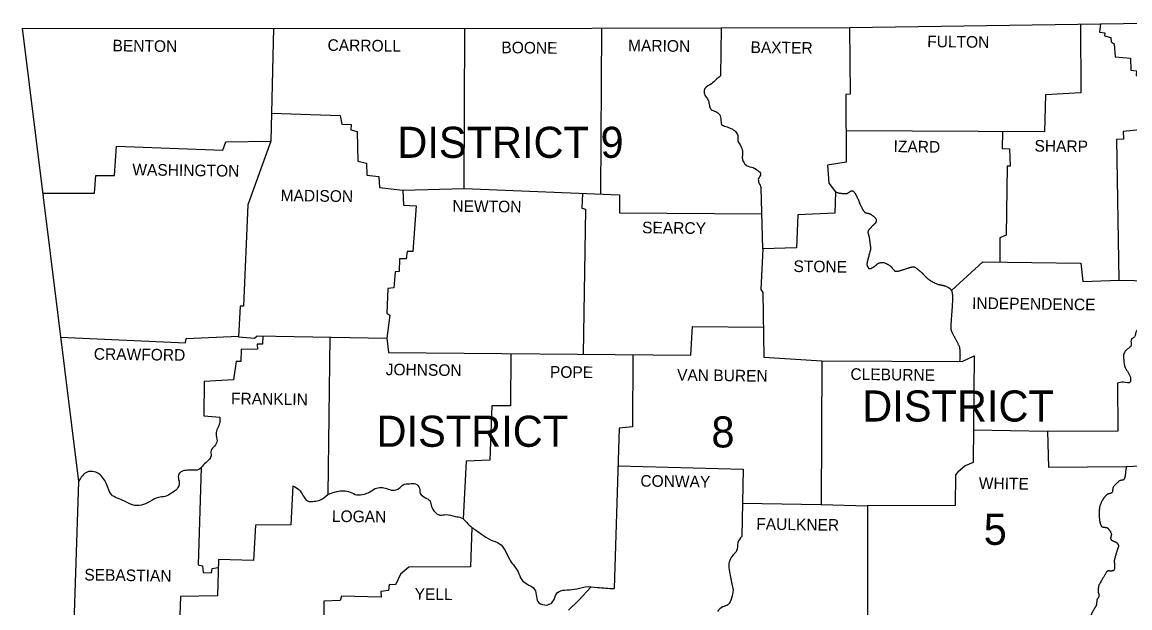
# Model space of a CAD drawing. Extents: x -0.96 to 2.36, y -0.12 to 0.92.
# Drawn here: x 1.0951 to 1.2805, y 0.7208 to 0.8188 of the extents above; entities that cross this region are included whole.
import ezdxf

# ---------------------------------------------------------------- set-up
doc = ezdxf.new("R2010")
doc.units = 0
doc.layers.add('SHET_Annotations', color=7, linetype='Continuous')

msp = doc.modelspace()

# ---------------------------------------------------------------- linework, layer by layer
at = {"layer": 'SHET_Annotations'}
msp.add_line((1.27998, 0.74445), (1.28519, 0.74474), dxfattribs=at)
for points in [[(1.0951, 0.81784), (1.16886, 0.81779), (1.23364, 0.81792), (1.31002, 0.81908), (1.34545, 0.81991)], [(1.0951, 0.81784), (1.10454, 0.74198), (1.10045, 0.61817)], [(1.1372, 0.81781), (1.13672, 0.79894)], [(1.19207, 0.81783), (1.19191, 0.79004)], [(1.21215, 0.81787), (1.21204, 0.80983)], [(1.23361, 0.81792), (1.23372, 0.80679), (1.23297, 0.80674), (1.23307, 0.79538), (1.22991, 0.79491), (1.23017, 0.79188), (1.23126, 0.79045), (1.23118, 0.78685), (1.22498, 0.78661), (1.22475, 0.78106), (1.21909, 0.78088), (1.21878, 0.77409), (1.21912, 0.77357), (1.21928, 0.76278), (1.229, 0.76213), (1.22887, 0.73809), (1.23665, 0.73788), (1.23665, 0.7134), (1.23053, 0.71293), (1.23009, 0.70759), (1.21979, 0.70751)], [(1.27228, 0.81851), (1.27236, 0.80702), (1.26642, 0.80669), (1.26627, 0.80049), (1.23302, 0.80065)], [(1.27561, 0.81856), (1.27545, 0.81716), (1.27636, 0.81703), (1.27628, 0.81652), (1.27734, 0.81628), (1.27742, 0.81553), (1.27794, 0.81522), (1.27807, 0.81304), (1.28066, 0.81278), (1.28069, 0.81078), (1.28165, 0.81068), (1.28162, 0.8099), (1.28245, 0.80964), (1.28243, 0.807), (1.28313, 0.80687), (1.28331, 0.8009), (1.27944, 0.80054), (1.2795, 0.79927), (1.27833, 0.79919), (1.27872, 0.77567), (1.2971, 0.77525), (1.29742, 0.73864), (1.28541, 0.73832), (1.28519, 0.74474)], [(1.13684, 0.80358), (1.14835, 0.80321), (1.14861, 0.80176), (1.15019, 0.80171), (1.15014, 0.80083), (1.1512, 0.80054), (1.1513, 0.79554), (1.15273, 0.79522), (1.15283, 0.79325), (1.1548, 0.79299), (1.15491, 0.79115), (1.15885, 0.79073), (1.16912, 0.791), (1.1692, 0.81779)], [(1.25922, 0.80052), (1.25916, 0.79769), (1.26041, 0.79761), (1.26049, 0.79471), (1.25999, 0.79471), (1.25984, 0.78319), (1.25877, 0.78272), (1.25877, 0.77869)], [(1.09854, 0.79022), (1.10724, 0.79019), (1.10745, 0.79318), (1.11059, 0.79318), (1.11087, 0.79805), (1.12869, 0.79743), (1.12921, 0.79878), (1.13672, 0.79894), (1.13289, 0.78825), (1.13214, 0.77131), (1.13159, 0.77129), (1.13133, 0.76618), (1.134, 0.76594), (1.13442, 0.76636), (1.15618, 0.76594), (1.15641, 0.76353)], [(1.15885, 0.79073), (1.15895, 0.7882), (1.16105, 0.78809), (1.16051, 0.78042), (1.15955, 0.78044), (1.15937, 0.77922), (1.15828, 0.7792), (1.15823, 0.77712), (1.15755, 0.77707), (1.15732, 0.77437), (1.15631, 0.77424), (1.15618, 0.77015), (1.15664, 0.76981), (1.15618, 0.76594)], [(1.16912, 0.791), (1.19511, 0.78991), (1.19508, 0.78693), (1.21895, 0.78677)], [(1.18889, 0.79017), (1.1888, 0.78768), (1.18943, 0.78752), (1.18903, 0.76325)], [(1.21909, 0.78088), (1.21883, 0.79113)], [(1.25066, 0.77392), (1.25595, 0.77873), (1.27236, 0.77847), (1.27267, 0.77544), (1.27872, 0.77567)], [(1.15641, 0.76353), (1.20706, 0.76309), (1.20732, 0.76792), (1.2192, 0.76776)], [(1.10154, 0.76613), (1.12246, 0.76514), (1.12257, 0.76589), (1.13134, 0.76629)], [(1.13537, 0.76634), (1.13533, 0.76493), (1.13447, 0.76493), (1.1345, 0.7641), (1.13175, 0.76405), (1.1317, 0.76203), (1.13092, 0.76203), (1.13048, 0.75897), (1.12555, 0.75871), (1.12552, 0.75295), (1.12817, 0.75274)], [(1.14661, 0.76613), (1.14627, 0.73978)], [(1.1769, 0.76335), (1.17685, 0.75464), (1.17371, 0.75459), (1.17342, 0.74551), (1.16943, 0.74535), (1.16895, 0.73569)], [(1.19736, 0.76318), (1.19728, 0.75108), (1.19505, 0.75088), (1.19422, 0.72403)], [(1.229, 0.76213), (1.25247, 0.76203), (1.25447, 0.76296), (1.25434, 0.74515), (1.25299, 0.74455), (1.25175, 0.74349), (1.25136, 0.74307), (1.25128, 0.73796), (1.23665, 0.73788)], [(1.27848, 0.75842), (1.27856, 0.75038), (1.26674, 0.75033), (1.25438, 0.75057)], [(1.26674, 0.75033), (1.26692, 0.74434), (1.27998, 0.74445)], [(1.12507, 0.74427), (1.12459, 0.728), (1.12532, 0.72782), (1.12542, 0.72673), (1.12682, 0.72665), (1.12692, 0.72741), (1.12792, 0.72757)], [(1.19486, 0.74455), (1.21583, 0.74403), (1.21557, 0.73277)], [(1.27998, 0.74445), (1.27986, 0.74395)], [(1.14041, 0.74123), (1.1401, 0.73472), (1.13416, 0.73467), (1.13382, 0.72873), (1.12796, 0.72888), (1.12778, 0.72279), (1.12161, 0.72271), (1.1214, 0.71659), (1.12532, 0.71638), (1.12516, 0.71449), (1.14557, 0.71393)], [(1.21569, 0.7383), (1.22887, 0.73809)], [(1.17039, 0.73425), (1.17018, 0.72769), (1.15981, 0.72764), (1.15843, 0.72647), (1.15763, 0.72466), (1.15652, 0.72471), (1.15646, 0.7237), (1.15514, 0.72354), (1.15519, 0.72261), (1.14858, 0.72276), (1.14832, 0.72204), (1.1456, 0.72193), (1.14557, 0.71393)], [(1.19036, 0.7243), (1.18831, 0.72209), (1.18655, 0.7204)]]:
    msp.add_lwpolyline(points, dxfattribs=at)
for points in [[(1.21204, 0.80983), (1.21121, 0.80918), (1.21051, 0.80853), (1.20939, 0.80772), (1.20927, 0.807), (1.20963, 0.8063), (1.20999, 0.8057), (1.21015, 0.80487), (1.21046, 0.8042), (1.21121, 0.80389), (1.21188, 0.80332), (1.21209, 0.80251), (1.2122, 0.80173), (1.2129, 0.80137), (1.21373, 0.80106), (1.21453, 0.80051), (1.21489, 0.79987), (1.21494, 0.79896), (1.21528, 0.79831), (1.21565, 0.79745), (1.21572, 0.79678), (1.21565, 0.79611), (1.21585, 0.79546), (1.21642, 0.79481), (1.21746, 0.7945), (1.21821, 0.79406), (1.21873, 0.79341), (1.21837, 0.79266), (1.21845, 0.79196), (1.21883, 0.79113)], [(1.28698, 0.77548), (1.28613, 0.77341), (1.28546, 0.77204), (1.28507, 0.77085), (1.28419, 0.77017), (1.2839, 0.76952), (1.28315, 0.76926), (1.28256, 0.76836), (1.2823, 0.76755), (1.28165, 0.76719), (1.28131, 0.76615), (1.28074, 0.76561), (1.28077, 0.7647), (1.28009, 0.76408), (1.27955, 0.76335), (1.27952, 0.76231), (1.27978, 0.76102), (1.28025, 0.76021), (1.28064, 0.75923), (1.28061, 0.75858), (1.27947, 0.75858), (1.27848, 0.75842)], [(1.12817, 0.75274), (1.12817, 0.75178), (1.12781, 0.7508), (1.12757, 0.74992), (1.12773, 0.74878), (1.12731, 0.74787), (1.12672, 0.74712), (1.12672, 0.74623), (1.12604, 0.74527), (1.12529, 0.74452), (1.12467, 0.74395), (1.1235, 0.74387), (1.12254, 0.74382), (1.12161, 0.74349), (1.12124, 0.74279), (1.1214, 0.74175), (1.12104, 0.74074), (1.1201, 0.73998), (1.11904, 0.73947), (1.11795, 0.73928), (1.11642, 0.73856), (1.11507, 0.73799), (1.11359, 0.73804), (1.11225, 0.73864), (1.111, 0.73918), (1.11004, 0.73975), (1.10929, 0.74141), (1.10877, 0.74234), (1.10789, 0.74328), (1.10688, 0.74364), (1.106, 0.74354), (1.10454, 0.74198)], [(1.14041, 0.74123), (1.1414, 0.74061), (1.14217, 0.73957), (1.14285, 0.73869), (1.14401, 0.73864), (1.14492, 0.73882), (1.14627, 0.73978)], [(1.14627, 0.73978), (1.1478, 0.74027), (1.14889, 0.7404), (1.15001, 0.74019), (1.15115, 0.73972), (1.15234, 0.73985), (1.15325, 0.74017), (1.15418, 0.74076), (1.15517, 0.74094), (1.15615, 0.74076), (1.15716, 0.74048), (1.15823, 0.74081), (1.15888, 0.74138), (1.15996, 0.74159), (1.16095, 0.74159), (1.16162, 0.74081), (1.16175, 0.73996), (1.16264, 0.73921), (1.16339, 0.73869), (1.16365, 0.73775), (1.16404, 0.73705), (1.16445, 0.73659), (1.16505, 0.73633), (1.16606, 0.73641), (1.16761, 0.73609), (1.1686, 0.73589), (1.16953, 0.73508), (1.17039, 0.73425)], [(1.17039, 0.73425), (1.172, 0.73316), (1.1735, 0.7322), (1.17503, 0.73153), (1.17589, 0.73054), (1.17667, 0.72896), (1.17734, 0.728), (1.17812, 0.72681), (1.17874, 0.72551), (1.17967, 0.72476), (1.18069, 0.72414), (1.18118, 0.723), (1.18141, 0.72186), (1.18253, 0.72129), (1.18359, 0.72152), (1.18416, 0.72222), (1.18473, 0.72339), (1.18595, 0.72378), (1.18753, 0.72391), (1.18935, 0.72432), (1.1914, 0.72424), (1.19422, 0.72403)], [(1.21557, 0.73277), (1.21494, 0.73171), (1.21471, 0.73034), (1.21396, 0.72946), (1.21349, 0.7285), (1.21347, 0.72715), (1.21367, 0.72595), (1.21391, 0.72484), (1.21411, 0.72378), (1.21386, 0.72245), (1.21326, 0.72131), (1.21238, 0.72097), (1.2115, 0.7202)]]:
    msp.add_spline(points, degree=3, dxfattribs=at)
for points in [[(1.23126, 0.79045), (1.2314, 0.79038), (1.23155, 0.79032), (1.2317, 0.79029), (1.23185, 0.79025), (1.23201, 0.79021), (1.23216, 0.7902), (1.23231, 0.79018), (1.23247, 0.79017), (1.23262, 0.79016), (1.23277, 0.79015), (1.23292, 0.79014), (1.23307, 0.79014), (1.23317, 0.79014), (1.23327, 0.79018), (1.23336, 0.79024), (1.23347, 0.7903), (1.23355, 0.79038), (1.23365, 0.79045), (1.23374, 0.7905), (1.23383, 0.79056), (1.23393, 0.7906), (1.23397, 0.79062), (1.23402, 0.79062), (1.23406, 0.79062), (1.23411, 0.79061), (1.23415, 0.79059), (1.23419, 0.79056), (1.23439, 0.79038), (1.23454, 0.7902), (1.23465, 0.78999), (1.23471, 0.78988), (1.23477, 0.78978), (1.23482, 0.78967), (1.23487, 0.78956), (1.23492, 0.78945), (1.23497, 0.78934), (1.2351, 0.78904), (1.23522, 0.78873), (1.23536, 0.78843), (1.23545, 0.7882), (1.23556, 0.78798), (1.23567, 0.78776), (1.23572, 0.78765), (1.23578, 0.78755), (1.23584, 0.78744), (1.23588, 0.78739), (1.23591, 0.78734), (1.23595, 0.78729), (1.23598, 0.78723), (1.23602, 0.78718), (1.23606, 0.78713), (1.23612, 0.78706), (1.23619, 0.78699), (1.23628, 0.78696), (1.23637, 0.78692), (1.23647, 0.78689), (1.23656, 0.78687), (1.23666, 0.78685), (1.23677, 0.78683), (1.23687, 0.7868), (1.23691, 0.78679), (1.23696, 0.78678), (1.23701, 0.78676), (1.23706, 0.78674), (1.2371, 0.78672), (1.23714, 0.78669), (1.2373, 0.7866), (1.23745, 0.78649), (1.23759, 0.78638), (1.23767, 0.78632), (1.23773, 0.78626), (1.2378, 0.7862), (1.23786, 0.78613), (1.23792, 0.78607), (1.23797, 0.78599), (1.23801, 0.78594), (1.23804, 0.78588), (1.23806, 0.78581), (1.23808, 0.78574), (1.23809, 0.78567), (1.23808, 0.7856), (1.23807, 0.7855), (1.23805, 0.78539), (1.238, 0.7853), (1.23799, 0.78527), (1.23797, 0.78524), (1.23795, 0.78521), (1.23789, 0.78515), (1.23784, 0.78508), (1.23778, 0.78503), (1.23772, 0.78497), (1.23765, 0.78491), (1.23759, 0.78485), (1.23753, 0.78479), (1.23746, 0.78474), (1.2374, 0.78468), (1.23734, 0.78462), (1.23728, 0.78455), (1.23722, 0.78449), (1.2372, 0.78446), (1.23717, 0.78443), (1.23714, 0.7844), (1.23706, 0.78431), (1.23697, 0.78422), (1.23689, 0.78413), (1.23684, 0.78408), (1.2368, 0.78401), (1.23676, 0.78394), (1.23674, 0.78391), (1.23673, 0.78388), (1.23672, 0.78384), (1.23671, 0.78381), (1.2367, 0.78377), (1.2367, 0.78374), (1.2367, 0.78366), (1.23671, 0.78359), (1.23672, 0.78352), (1.23674, 0.78344), (1.23676, 0.78337), (1.23678, 0.7833), (1.2368, 0.78322), (1.23682, 0.78315), (1.23684, 0.78308), (1.23685, 0.783), (1.23687, 0.78293), (1.23689, 0.78285), (1.23692, 0.78266), (1.23695, 0.78246), (1.23698, 0.78226), (1.23701, 0.78206), (1.23704, 0.78186), (1.23707, 0.78166), (1.23712, 0.78129), (1.23715, 0.78091), (1.23707, 0.78055), (1.23698, 0.78019), (1.23687, 0.77984), (1.23678, 0.77948), (1.2367, 0.77917), (1.23662, 0.77887), (1.23655, 0.77855), (1.23653, 0.77848), (1.23652, 0.7784), (1.23652, 0.77833), (1.23652, 0.77826), (1.23653, 0.77819), (1.23655, 0.77812), (1.23657, 0.77804), (1.2366, 0.77797), (1.23664, 0.7779), (1.23666, 0.77787), (1.23668, 0.77783), (1.2367, 0.7778), (1.23673, 0.77776), (1.23675, 0.77773), (1.23678, 0.77769), (1.23681, 0.77766), (1.23684, 0.77764), (1.23687, 0.77761), (1.23691, 0.77759), (1.23694, 0.77758), (1.23698, 0.77758), (1.23705, 0.77758), (1.23713, 0.77759), (1.2372, 0.77762), (1.23736, 0.77769), (1.2375, 0.77776), (1.23764, 0.77785), (1.23768, 0.77787), (1.23772, 0.7779), (1.23776, 0.77792), (1.2378, 0.77795), (1.23783, 0.77798), (1.23787, 0.77801), (1.23795, 0.77807), (1.23802, 0.77814), (1.23809, 0.7782), (1.23817, 0.77827), (1.23824, 0.77833), (1.23832, 0.77839), (1.2384, 0.77845), (1.23848, 0.77849), (1.23857, 0.77852), (1.23887, 0.77863), (1.23923, 0.77864), (1.23953, 0.77852), (1.23969, 0.77846), (1.23985, 0.77839), (1.24, 0.7783), (1.24015, 0.77822), (1.2403, 0.77813), (1.24044, 0.77803), (1.24053, 0.77796), (1.24061, 0.77789), (1.24068, 0.7778), (1.24075, 0.77771), (1.24081, 0.77761), (1.24089, 0.77752), (1.24096, 0.77744), (1.24103, 0.77735), (1.24111, 0.77728), (1.24114, 0.77724), (1.24119, 0.77722), (1.24123, 0.77719), (1.24125, 0.77718), (1.24128, 0.77717), (1.2413, 0.77716), (1.24132, 0.77716), (1.24135, 0.77715), (1.24137, 0.77715), (1.24153, 0.77713), (1.2417, 0.77714), (1.24185, 0.77719), (1.24201, 0.77723), (1.24217, 0.77728), (1.24233, 0.77733), (1.2426, 0.77742), (1.24287, 0.7775), (1.24314, 0.77759), (1.24332, 0.77765), (1.2435, 0.7777), (1.24368, 0.77776), (1.24377, 0.77779), (1.24386, 0.77781), (1.24395, 0.77783), (1.244, 0.77784), (1.24404, 0.77785), (1.24409, 0.77786), (1.24413, 0.77786), (1.24418, 0.77787), (1.24422, 0.77787), (1.24436, 0.77788), (1.24451, 0.77784), (1.24463, 0.77776), (1.24476, 0.77767), (1.24488, 0.77758), (1.245, 0.77749), (1.24512, 0.7774), (1.24524, 0.77731), (1.24535, 0.77722), (1.24546, 0.77713), (1.24557, 0.77704), (1.24568, 0.77694), (1.24575, 0.77687), (1.24582, 0.7768), (1.24589, 0.77673), (1.24596, 0.77666), (1.24602, 0.77658), (1.24609, 0.77651), (1.24616, 0.77644), (1.24622, 0.77637), (1.24629, 0.77629), (1.24636, 0.77622), (1.24643, 0.77615), (1.24651, 0.77608), (1.24675, 0.77587), (1.24701, 0.77568), (1.24728, 0.77551), (1.2476, 0.77532), (1.24793, 0.77516), (1.24827, 0.77502), (1.24837, 0.77498), (1.24847, 0.77495), (1.24857, 0.77492), (1.24868, 0.7749), (1.24878, 0.77488), (1.24889, 0.77486), (1.24899, 0.77484), (1.2491, 0.77482), (1.2492, 0.7748), (1.24931, 0.77478), (1.24941, 0.77474), (1.24952, 0.77471), (1.24974, 0.77464), (1.24995, 0.77455), (1.25016, 0.77443), (1.25027, 0.77437), (1.25036, 0.7743), (1.25044, 0.77422), (1.25049, 0.77418), (1.25052, 0.77414), (1.25056, 0.77409), (1.25058, 0.77406), (1.25059, 0.77404), (1.25061, 0.77401), (1.25063, 0.77399), (1.25064, 0.77396), (1.25066, 0.77393), (1.25068, 0.77388), (1.25071, 0.77383), (1.25073, 0.77377), (1.25078, 0.77361), (1.25082, 0.77344), (1.25083, 0.77327), (1.25084, 0.77316), (1.25084, 0.77305), (1.25084, 0.77294), (1.25084, 0.77283), (1.25084, 0.77272), (1.25084, 0.77261), (1.25084, 0.77242), (1.25084, 0.77223), (1.25083, 0.77204), (1.25083, 0.77185), (1.25082, 0.77166), (1.25081, 0.77147), (1.25078, 0.77099), (1.25074, 0.77052), (1.25071, 0.77004), (1.25067, 0.76953), (1.25064, 0.76902), (1.2506, 0.76851), (1.2506, 0.76838), (1.25059, 0.76825), (1.25058, 0.76813), (1.25057, 0.768), (1.25057, 0.76787), (1.25057, 0.76774), (1.25057, 0.76761), (1.25058, 0.76748), (1.25061, 0.76735), (1.25064, 0.76722), (1.25068, 0.7671), (1.25073, 0.76698), (1.25082, 0.76681), (1.2509, 0.76665), (1.25099, 0.76648), (1.25108, 0.76632), (1.25117, 0.76616), (1.25125, 0.766), (1.25136, 0.7658), (1.25146, 0.7656), (1.25156, 0.7654), (1.25167, 0.7652), (1.25177, 0.765), (1.25188, 0.7648), (1.25196, 0.76463), (1.25201, 0.76445), (1.25203, 0.76426), (1.25205, 0.76416), (1.25206, 0.76407), (1.25206, 0.76397), (1.25207, 0.76388), (1.25208, 0.76378), (1.25208, 0.76369), (1.2521, 0.76341), (1.25211, 0.76314), (1.25211, 0.76286), (1.2521, 0.76258), (1.25208, 0.7623), (1.25204, 0.76203)], [(1.27986, 0.74395), (1.27985, 0.74382), (1.27984, 0.7437), (1.27983, 0.74357), (1.27982, 0.74344), (1.27981, 0.74331), (1.27979, 0.74318), (1.27978, 0.74305), (1.27976, 0.74293), (1.27973, 0.7428), (1.27972, 0.74274), (1.2797, 0.74267), (1.27968, 0.74261), (1.27968, 0.74258), (1.27967, 0.74255), (1.27966, 0.74252), (1.27965, 0.74248), (1.27964, 0.74245), (1.27962, 0.74242), (1.2796, 0.74235), (1.27954, 0.74229), (1.27948, 0.74225), (1.2794, 0.74221), (1.27932, 0.74219), (1.27924, 0.74217), (1.27915, 0.74215), (1.27906, 0.74214), (1.27897, 0.74211), (1.27893, 0.7421), (1.27889, 0.74209), (1.27885, 0.74207), (1.27881, 0.74205), (1.27878, 0.74203), (1.27874, 0.74201), (1.27856, 0.74186), (1.2784, 0.74171), (1.27823, 0.74154), (1.27807, 0.74138), (1.27792, 0.74122), (1.27778, 0.74102), (1.27774, 0.74095), (1.2777, 0.74088), (1.27769, 0.7408), (1.27768, 0.74072), (1.27767, 0.74063), (1.27766, 0.74055), (1.27765, 0.74046), (1.27764, 0.74038), (1.27763, 0.7403), (1.27762, 0.74022), (1.27758, 0.74015), (1.27752, 0.74009), (1.27747, 0.74003), (1.27742, 0.73999), (1.27735, 0.73997), (1.27727, 0.73995), (1.2772, 0.73993), (1.27713, 0.73991), (1.27706, 0.73989), (1.27698, 0.73988), (1.27691, 0.73986), (1.27684, 0.73984), (1.27677, 0.7398), (1.27672, 0.73975), (1.27664, 0.73968), (1.27657, 0.73961), (1.27649, 0.73953), (1.27642, 0.73945), (1.27635, 0.73938), (1.27628, 0.7393), (1.27621, 0.73921), (1.27615, 0.73913), (1.27609, 0.73904), (1.27602, 0.73895), (1.27597, 0.73886), (1.27592, 0.73877), (1.2758, 0.73856), (1.27571, 0.73834), (1.27562, 0.73812), (1.27554, 0.7379), (1.27547, 0.73767), (1.27545, 0.73744), (1.27541, 0.73699), (1.2754, 0.73654), (1.27542, 0.73609), (1.27543, 0.73596), (1.27544, 0.73583), (1.27545, 0.7357), (1.27546, 0.73557), (1.27548, 0.73544), (1.2755, 0.73531), (1.27552, 0.73518), (1.27555, 0.73505), (1.27559, 0.73492), (1.27561, 0.73486), (1.27563, 0.73479), (1.27565, 0.73473), (1.27568, 0.73466), (1.2757, 0.7346), (1.27573, 0.73454), (1.27578, 0.73445), (1.27586, 0.73438), (1.27595, 0.73435), (1.27605, 0.73433), (1.27616, 0.73431), (1.27627, 0.7343), (1.27638, 0.73428), (1.27649, 0.73428), (1.2766, 0.73426), (1.2767, 0.73425), (1.2768, 0.7342), (1.27688, 0.73412), (1.27691, 0.73409), (1.27694, 0.73406), (1.27696, 0.73402), (1.27699, 0.73399), (1.27702, 0.73396), (1.27705, 0.73392), (1.2771, 0.73385), (1.27715, 0.73378), (1.2772, 0.7337), (1.27729, 0.73356), (1.27736, 0.73341), (1.27742, 0.73324), (1.27745, 0.73316), (1.27745, 0.73308), (1.27744, 0.73301), (1.27742, 0.73292), (1.2774, 0.73284), (1.27738, 0.73275), (1.27736, 0.73267), (1.27735, 0.73259), (1.27733, 0.73251), (1.27732, 0.73243), (1.27734, 0.73236), (1.27737, 0.73228), (1.27739, 0.73223), (1.27742, 0.7322), (1.27746, 0.73216), (1.2775, 0.73213), (1.27753, 0.7321), (1.27758, 0.73208), (1.27768, 0.73203), (1.27778, 0.73199), (1.27788, 0.73195), (1.27798, 0.73191), (1.27809, 0.73187), (1.27819, 0.73182), (1.27829, 0.73178), (1.27837, 0.7317), (1.27843, 0.73161), (1.27846, 0.73157), (1.27849, 0.73152), (1.27852, 0.73148), (1.27854, 0.73144), (1.27857, 0.73139), (1.27859, 0.73135), (1.27862, 0.73131), (1.27863, 0.73127), (1.27864, 0.73122), (1.27865, 0.73118), (1.27865, 0.73113), (1.27864, 0.73109), (1.27863, 0.73104), (1.27861, 0.73099), (1.27859, 0.73094), (1.27858, 0.73089), (1.27856, 0.73084), (1.27854, 0.73079), (1.27852, 0.73074), (1.2785, 0.73069), (1.27848, 0.73064), (1.27846, 0.73059), (1.27845, 0.73054), (1.27843, 0.73049), (1.27834, 0.73022), (1.27826, 0.72994), (1.27818, 0.72966), (1.2781, 0.72938), (1.27803, 0.7291), (1.27796, 0.72881), (1.27794, 0.72871), (1.27794, 0.72862), (1.27794, 0.72852), (1.27794, 0.72843), (1.27795, 0.72833), (1.27795, 0.72824), (1.27796, 0.72814), (1.27797, 0.72805), (1.27798, 0.72795), (1.27799, 0.72786), (1.27799, 0.72776), (1.27799, 0.72767), (1.27799, 0.72758), (1.27798, 0.72749), (1.27797, 0.7274), (1.27796, 0.72736), (1.27795, 0.72732), (1.27794, 0.72727), (1.27792, 0.72723), (1.27791, 0.72719), (1.27789, 0.72715), (1.27783, 0.72706), (1.27775, 0.72698), (1.27765, 0.72698), (1.27753, 0.72697), (1.27741, 0.72697), (1.27729, 0.72697), (1.27717, 0.72697), (1.27705, 0.72698), (1.27693, 0.72698), (1.27683, 0.72698), (1.27672, 0.72692), (1.27667, 0.72684), (1.27653, 0.72663), (1.27641, 0.72642), (1.27629, 0.72622), (1.27616, 0.72601), (1.27604, 0.7258), (1.27592, 0.72559), (1.27575, 0.72531), (1.27559, 0.72502), (1.27542, 0.72473), (1.2754, 0.72469), (1.27538, 0.72464), (1.27536, 0.72459), (1.27531, 0.72445), (1.27528, 0.7243), (1.27527, 0.72415), (1.27526, 0.72406), (1.27525, 0.72396), (1.27525, 0.72386), (1.27525, 0.72376), (1.27524, 0.72367), (1.27524, 0.72357), (1.27524, 0.7235), (1.27525, 0.72344), (1.27526, 0.72337), (1.27528, 0.72331), (1.2753, 0.72324), (1.27532, 0.72318), (1.27534, 0.72311), (1.27535, 0.72305), (1.27537, 0.72298), (1.27538, 0.72292), (1.27538, 0.72285), (1.27537, 0.72279), (1.27536, 0.72273), (1.27534, 0.72267), (1.27531, 0.72261), (1.27528, 0.72256), (1.27525, 0.7225), (1.27521, 0.72245), (1.27518, 0.72239), (1.27514, 0.72234), (1.27511, 0.72229), (1.27508, 0.72223), (1.27505, 0.72218), (1.27503, 0.72212), (1.27501, 0.72204), (1.275, 0.72196), (1.27499, 0.72188), (1.27499, 0.7218), (1.27499, 0.72171), (1.27498, 0.72163), (1.27497, 0.72155), (1.27496, 0.72147), (1.27495, 0.72139), (1.27494, 0.72131), (1.27491, 0.72123), (1.27488, 0.72116), (1.27484, 0.72109), (1.27481, 0.72102), (1.27477, 0.72095), (1.27473, 0.72089), (1.27469, 0.72082), (1.27465, 0.72075), (1.27457, 0.72062), (1.27449, 0.72049), (1.27441, 0.72035), (1.27434, 0.72023), (1.27427, 0.72009), (1.27421, 0.71996), (1.27414, 0.71984), (1.27408, 0.71971), (1.27402, 0.71957), (1.27399, 0.7195), (1.274, 0.71941), (1.27405, 0.71934), (1.2741, 0.71926), (1.27416, 0.71919), (1.27422, 0.71911), (1.27428, 0.71903), (1.27434, 0.71897), (1.2744, 0.71888), (1.27445, 0.71881), (1.27448, 0.71872), (1.27446, 0.71864), (1.27445, 0.71854), (1.27443, 0.71843), (1.2744, 0.71833), (1.27438, 0.71823), (1.27436, 0.71812), (1.27433, 0.71802), (1.27426, 0.71769), (1.27412, 0.71737), (1.27407, 0.71703)]]:
    msp.add_open_spline(points, degree=3, dxfattribs=at)

# ---------------------------------------------------------------- texts
for s, height, rotation, p in [('CARROLL', 0.001945, 359.267, (1.14622, 0.81403)), ('FULTON', 0.001945, 359.282, (1.24661, 0.81465)), ('BENTON', 0.001945, 359.2874, (1.11022, 0.81395)), ('BOONE', 0.001945, 359.3139, (1.17532, 0.81364)), ('MARION', 0.001945, 359.2237, (1.19653, 0.81398)), ('BAXTER', 0.001945, 359.2892, (1.21703, 0.81367)), ('IZARD', 0.001945, 359.1987, (1.24098, 0.79709)), ('SHARP', 0.001945, 359.3013, (1.26457, 0.79717)), ('WASHINGTON', 0.001945, 359.2079, (1.11354, 0.7932)), ('MADISON', 0.001945, 359.217, (1.13836, 0.78888)), ('NEWTON', 0.001945, 359.303, (1.16712, 0.78711)), ('SEARCY', 0.001945, 359.2838, (1.19888, 0.7835)), ('STONE', 0.001945, 359.3139, (1.22423, 0.77702)), ('INDEPENDENCE', 0.0019451, 359.254, (1.25412, 0.77085)), ('CRAWFORD', 0.001945, 359.2748, (1.10709, 0.76234)), ('JOHNSON', 0.001945, 359.2575, (1.15595, 0.75975)), ('POPE', 0.001945, 359.3389, (1.18345, 0.75933)), ('VAN BUREN', 0.001945, 359.2547, (1.20473, 0.75884)), ('CLEBURNE', 0.001945, 359.2518, (1.23376, 0.75897)), ('FRANKLIN', 0.001945, 359.1782, (1.13006, 0.7549)), ('CONWAY', 0.001945, 359.1737, (1.19859, 0.7411)), ('WHITE', 0.001945, 359.2125, (1.25525, 0.74071)), ('LOGAN', 0.001945, 359.3076, (1.14695, 0.73519)), ('FAULKNER', 0.001945, 359.2447, (1.21799, 0.73389)), ('SEBASTIAN', 0.001945, 359.1959, (1.1055, 0.72539)), ('YELL', 0.001945, 359.3097, (1.1608, 0.72217))]:
    msp.add_text(s, height=height, rotation=rotation, dxfattribs=at).set_placement(p)
for s, height, p in [('DISTRICT 9', 0.005203, (1.15791, 0.79612)), ('DISTRICT', 0.005203, (1.23574, 0.75199)), ('DISTRICT', 0.005203, (1.15443, 0.74776)), ('8', 0.0052, (1.21049, 0.74765)), ('5', 0.0052, (1.25608, 0.73135))]:
    msp.add_text(s, height=height, dxfattribs=at).set_placement(p)

doc.saveas('drawing.dxf')
